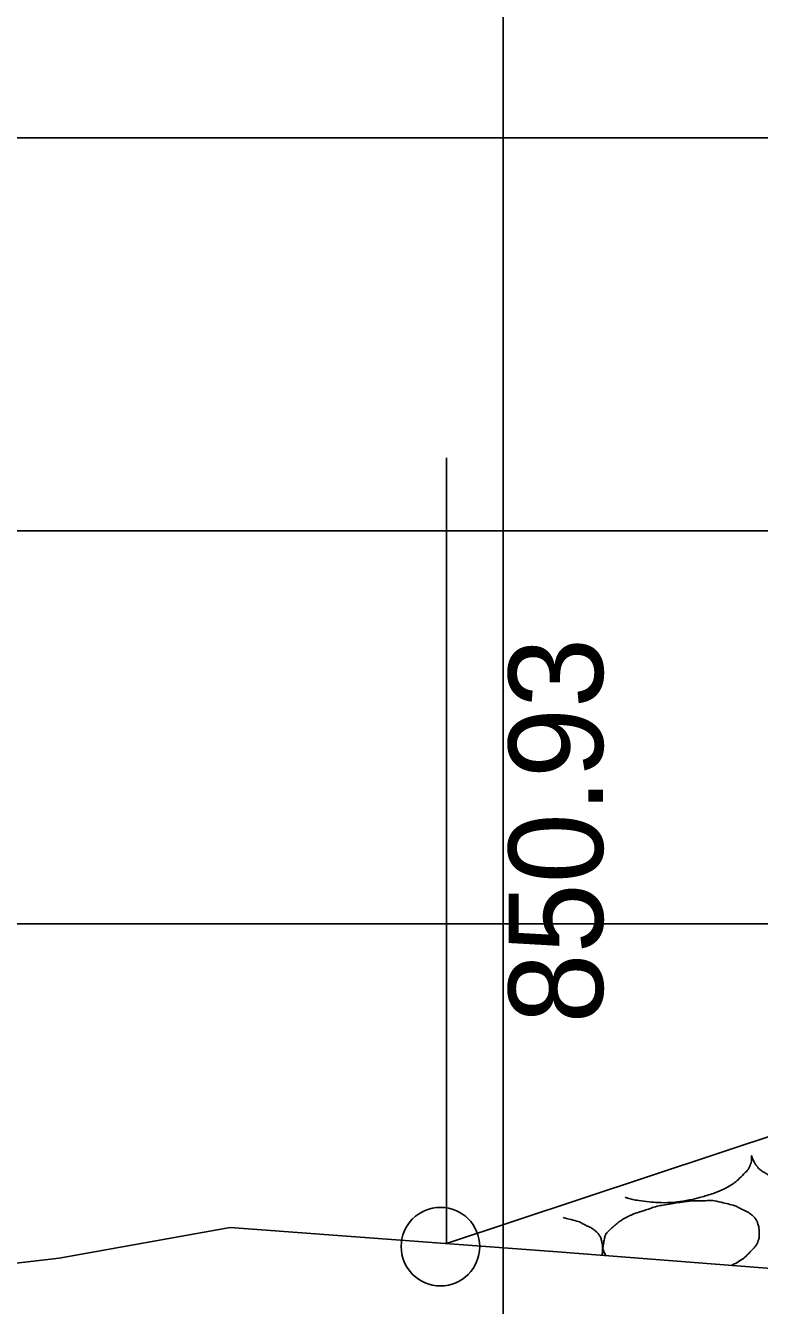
# Model space of a CAD drawing. Extents: x 1486524 to 1499135, y 326561 to 337924.
# Drawn here: x 1488896.81 to 1488906.14, y 335871.17 to 335887.45 of the extents above; entities that cross this region are included whole.
import ezdxf

# ---------------------------------------------------------------- set-up
doc = ezdxf.new("R2010")
doc.units = 0
for name, color, linetype in [('E_Ownership Information', 7, 'Continuous'), ('E_Proposed ROW Fig Annot', 7, 'Continuous'), ('E_Quarter Calls', 7, 'Continuous'), ('E_Title Sheet', 7, 'Continuous'), ('E_Tract Number', 7, 'Continuous'), ('R_Xsect Elev', 7, 'Continuous')]:
    doc.layers.add(name, color=color, linetype=linetype)

msp = doc.modelspace()

# ---------------------------------------------------------------- linework, layer by layer
at = {"layer": 'E_Ownership Information'}
for p, q in [((1488902.885, 335856.021), (1488902.885, 335906.021)), ((1488842.885, 335886.021), (1489122.885, 335886.021)), ((1488842.885, 335881.021), (1489122.885, 335881.021)), ((1488842.885, 335876.021), (1489122.885, 335876.021))]:
    msp.add_line(p, q, dxfattribs=at)
at = {"layer": 'E_Proposed ROW Fig Annot'}
for points in [[(1488906.05, 335873.074), (1488906.049, 335873.07), (1488906.049, 335873.065), (1488906.049, 335873.044), (1488906.058, 335873.029), (1488906.079, 335872.987), (1488906.092, 335872.963), (1488906.125, 335872.918), (1488906.142, 335872.899), (1488906.192, 335872.864), (1488906.224, 335872.847), (1488906.273, 335872.814), (1488906.29, 335872.796), (1488906.327, 335872.776), (1488906.345, 335872.777), (1488906.397, 335872.759), (1488906.431, 335872.739), (1488906.529, 335872.71), (1488906.59, 335872.7), (1488906.744, 335872.68), (1488906.834, 335872.671), (1488907.018, 335872.671), (1488907.11, 335872.683), (1488907.298, 335872.716), (1488907.394, 335872.74), (1488907.588, 335872.801), (1488907.681, 335872.841), (1488907.831, 335872.93), (1488907.879, 335872.975), (1488907.967, 335873.064), (1488908.002, 335873.102), (1488908.037, 335873.189), (1488908.037, 335873.224), (1488908.037, 335873.289), (1488908.035, 335873.319), (1488908.02, 335873.381), (1488908.008, 335873.412), (1488907.977, 335873.458), (1488907.964, 335873.472), (1488907.929, 335873.501), (1488907.911, 335873.516), (1488907.865, 335873.54), (1488907.839, 335873.55), (1488907.784, 335873.576), (1488907.757, 335873.599), (1488907.713, 335873.61), (1488907.702, 335873.613), (1488907.691, 335873.616)], [(1488904.436, 335872.543), (1488904.449, 335872.537), (1488904.461, 335872.532), (1488904.535, 335872.511), (1488904.596, 335872.501), (1488904.75, 335872.481), (1488904.841, 335872.472), (1488905.024, 335872.472), (1488905.116, 335872.484), (1488905.304, 335872.516), (1488905.4, 335872.541), (1488905.594, 335872.601), (1488905.688, 335872.641), (1488905.838, 335872.73), (1488905.885, 335872.776), (1488905.973, 335872.865), (1488906.009, 335872.902), (1488906.043, 335872.99), (1488906.044, 335873.024), (1488906.043, 335873.064), (1488906.043, 335873.068), (1488906.043, 335873.072)], [(1488905.789, 335871.674), (1488905.818, 335871.689), (1488905.847, 335871.704), (1488905.935, 335871.757), (1488905.983, 335871.802), (1488906.07, 335871.891), (1488906.106, 335871.928), (1488906.141, 335872.016), (1488906.141, 335872.051), (1488906.141, 335872.116), (1488906.139, 335872.146), (1488906.124, 335872.208), (1488906.112, 335872.239), (1488906.081, 335872.285), (1488906.067, 335872.299), (1488906.033, 335872.328), (1488906.015, 335872.343), (1488905.968, 335872.367), (1488905.942, 335872.377), (1488905.888, 335872.403), (1488905.861, 335872.426), (1488905.76, 335872.452), (1488905.692, 335872.469), (1488905.563, 335872.502), (1488905.499, 335872.498), (1488905.35, 335872.497), (1488905.263, 335872.496), (1488905.117, 335872.475), (1488905.056, 335872.464), (1488904.931, 335872.442), (1488904.867, 335872.434), (1488904.772, 335872.407), (1488904.739, 335872.393), (1488904.661, 335872.367), (1488904.616, 335872.354), (1488904.52, 335872.321), (1488904.47, 335872.296), (1488904.392, 335872.253), (1488904.364, 335872.234), (1488904.302, 335872.185), (1488904.27, 335872.155), (1488904.222, 335872.11), (1488904.206, 335872.096), (1488904.194, 335872.078)], [(1488904.14, 335871.802), (1488904.147, 335871.83), (1488904.147, 335871.858), (1488904.147, 335871.916), (1488904.145, 335871.946), (1488904.131, 335872.008), (1488904.119, 335872.039), (1488904.087, 335872.086), (1488904.074, 335872.099), (1488904.039, 335872.128), (1488904.021, 335872.144), (1488903.975, 335872.167), (1488903.949, 335872.177), (1488903.894, 335872.204), (1488903.867, 335872.227), (1488903.772, 335872.251), (1488903.71, 335872.267), (1488903.647, 335872.283)], [(1488904.21, 335872.098), (1488904.193, 335872.08), (1488904.181, 335872.053), (1488904.17, 335872.007), (1488904.166, 335871.987), (1488904.158, 335871.94), (1488904.153, 335871.913), (1488904.153, 335871.871), (1488904.162, 335871.855), (1488904.177, 335871.826), (1488904.184, 335871.812), (1488904.192, 335871.798)]]:
    msp.add_open_spline(points, degree=3, dxfattribs=at)
at = {"layer": 'E_Quarter Calls'}
msp.add_circle((1488902.085, 335871.913), 0.5, dxfattribs=at)
at = {"layer": 'E_Title Sheet'}
msp.add_lwpolyline([(1488902.16, 335871.951), (1488907.342, 335873.67), (1488924.342, 335879.685), (1488930.477, 335880.123), (1488930.429, 335881.512), (1488934.885, 335882.849), (1488935.543, 335883.014), (1488940.885, 335884.349), (1488945.425, 335885.484), (1488945.992, 335885.626)], dxfattribs=at)
at = {"layer": 'E_Tract Number'}
msp.add_lwpolyline([(1488895.047, 335871.514), (1488897.233, 335871.767), (1488899.409, 335872.155), (1488903.573, 335871.846), (1488909.335, 335871.399), (1488910.281, 335871.31), (1488911.942, 335871.813), (1488915.269, 335873.199), (1488918.715, 335875.585), (1488921.239, 335876.1), (1488927.551, 335877.207), (1488933.546, 335877.873), (1488935.434, 335878.728), (1488942.223, 335880.469), (1488945.464, 335881.203), (1488948.865, 335881.421)], dxfattribs=at)
at = {"layer": 'R_Xsect Elev'}
msp.add_line((1488902.16, 335871.951), (1488902.16, 335881.951), dxfattribs=at)

# ---------------------------------------------------------------- texts
msp.add_text('850.93', height=1.2, rotation=90, dxfattribs=at).set_placement((1488904.152, 335874.751))

doc.saveas('drawing.dxf')
